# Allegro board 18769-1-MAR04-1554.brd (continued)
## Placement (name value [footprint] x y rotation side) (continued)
PU5301  RT5797ALGQW-GP  [DFN8-G125065H32]  25.77 47.3 270 bottom
PU8551  RT8816BGQW-GP  [QFN20-G1D75H32]  145.41 28.88 90 bottom
PU8552  FDMS3600-02-RJK0215-COLAY-GP  [PPAK-8P-G5324H44-COLAY]  150.71 35.74 270 bottom
PU8553  FDMS3600-02-RJK0215-COLAY-GP  [PPAK-8P-G5324H44-COLAY]  150.71 35.74 90 top
PU8554  FDMS3600-02-RJK0215-COLAY-GP  [PPAK-8P-G5324H44-COLAY]  138.9 35.74 90 bottom
PU8555  FDMS3600-02-RJK0215-COLAY-GP  [PPAK-8P-G5324H44-COLAY]  138.9 35.74 270 top
PU8601  RT5797ALGQW-GP  [DFN8-G125065H32]  134.13 79.38 270 bottom
PU8602  SY8288RAC-GP  [QFN20Z3-G1H36]  178.88 35.77 90 bottom
PU8603  RT5797ALGQW-GP  [DFN8-G125065H32]  139.04 85.8 90 bottom
Q401  2N7002KDW-1-GP  [SOT-363H44]  127.88 63.58 270 bottom
Q501  PJA138KA-GP  [SOT23DGS2D4H44]  52.31 38.52 180 bottom
Q502  2N7002K-2-GP  [SOT23DGS2D4H44]  50.88 41.17 0 bottom
Q1701  PJT138KA-GP  [SOT-363H44]  128.1 64.39 270 top
Q1702  2N7002KDW-1-GP  [SOT-363H44]  128.38 61.16 270 top
Q2408  2N7002K-2-GP  [SOT23DGS2D4H44]  23.74 15.33 0 top
Q2414  2N7002K-2-GP  [SOT23DGS2D4H44]  44.02 14.37 270 top
Q2416  2N7002KDW-1-GP  [SOT-363H44]  12.4 20.77 0 bottom
Q2505  2N7002K-2-GP  [SOT23DGS2D4H44]  13.08 8.63 180 bottom
Q2507  SM2421PSANC-TRG-GP  [SOT23DGS2D4H48]  20.21 4.65 90 bottom
Q2510  2N7002K-2-GP  [SOT23DGS2D4H44]  23.58 11.35 90 top
Q2601  2N7002KDW-1-GP  [SOT-363H44]  125.85 45.72 180 bottom
Q2602  2N7002K-2-GP  [SOT23DGS2D4H44]  126.68 44.24 0 top
Q2603  LMBT3904LT1G-GP  [SOT23CBE2D4H44]  94.81 78.35 0 bottom
Q4001  2N7002K-2-GP  [SOT23DGS2D4H44]  186.8 23.27 270 top
Q4002  PJA3415-GP  [SOT23DGS2D4H44]  195.19 15.44 180 bottom
Q4301  PJA138KA-GP  [SOT23DGS2D4H44]  28.1 51.53 180 bottom
Q4302  LMBT3904LT1G-GP  [SOT23CBE2D4H44]  31.54 52.42 0 bottom
Q4304  LMUN5212T1G-GP  [SOT323CBE2D2H40]  20.81 76.86 0 top
Q4305  LMUN5112T1G-GP-U  [SOT323CBE2D2H40]  29.67 81.64 90 top
Q5508  LMBT3904LT1G-GP  [SOT23CBE2D4H44]  41.16 75.42 180 top
Q5509  MMBT3906-3-GP  [SOT23CBE2D4H44]  37.04 69.25 270 top
Q5510  LMBT3904LT1G-GP  [SOT23CBE2D4H44]  43.75 76.15 180 bottom
Q5512  MMBT3906-3-GP  [SOT23CBE2D4H44]  47.18 72.65 180 bottom
Q5701  LMBT3904LT1G-GP  [SOT23CBE2D4H44]  16.44 59.05 270 bottom
Q5702  2N7002KDW-1-GP  [SOT-363H44]  15.46 55.81 180 bottom
Q5703  2N7002K-2-GP  [SOT23DGS2D4H44]  20.88 44.7 180 bottom
Q6401  LDTA144VLT1G-GP  [SOT23CBE2D4H44]  9.98 71.33 270 bottom
Q6402  LDTA144VLT1G-GP  [SOT23CBE2D4H44]  5.7 71.29 270 bottom
Q6403  PJA138KA-GP  [SOT23DGS2D4H44]  11.69 70.55 270 top
Q6404  PJT138KA-GP  [SOT-363H44]  13.86 71.16 270 bottom
Q6406  LMBT3904LT1G-GP  [SOT23CBE2D4H44]  17.29 65.75 180 bottom
Q6407  LMUN5112T1G-GP-U  [SOT323CBE2D2H40]  17.09 71.35 180 bottom
Q6501  PJA3402-R1-00001-GP  [SOT23DGS2D4H44]  36.49 10.29 270 bottom
Q6504  2N7002KDW-1-GP  [SOT-363H44]  124.55 12 180 bottom
Q6505  LDTA144VLT1G-GP  [SOT23CBE2D4H44]  50.35 11.14 90 bottom
Q6701  2N7002KDW-1-GP  [SOT-363H44]  15.39 52.23 180 bottom
Q7401  PJA3415-GP  [SOT23DGS2D4H44]  22.42 63.99 180 top
Q7404  2N7002KDW-1-GP  [SOT-363H44]  26.47 67.49 270 top
Q7405  2N7002KDW-1-GP  [SOT-363H44]  23.62 68.29 0 top
Q7406  PJT138KA-GP  [SOT-363H44]  20.77 69.75 180 top
Q7407  PJT138KA-GP  [SOT-363H44]  20.6 68.66 270 bottom
Q7601  PJA138KA-GP  [SOT23DGS2D4H44]  139.05 54.89 0 top
Q7901  PJT138KA-GP  [SOT-363H44]  137.73 51.49 90 top
Q7906  PJA138KA-GP  [SOT23DGS2D4H44]  139.05 57.39 0 top
Q7907  PJT138KA-GP  [SOT-363H44]  140.6 49.48 270 top
Q8101  PJA138KA-GP  [SOT23DGS2D4H44]  171.36 54.36 180 bottom
Q8504  2N7002K-2-GP  [SOT23DGS2D4H44]  144.52 77.85 180 bottom
Q8509  PJT138KA-GP  [SOT-363H44]  142.98 80.38 0 bottom
Q8601  PJA138KA-GP  [SOT23DGS2D4H44]  128.06 69.9 90 bottom
Q8602  2N7002K-2-GP  [SOT23DGS2D4H44]  132 64.57 180 bottom
Q8603  2N7002K-2-GP  [SOT23DGS2D4H44]  130.92 68.23 180 bottom
Q8605  2N7002K-2-GP  [SOT23DGS2D4H44]  150.46 79.08 270 bottom
Q8611  PJA3415-GP  [SOT23DGS2D4H44]  130.14 74.87 270 bottom
Q8612  PJT138KA-GP  [SOT-363H44]  131.43 71.31 180 bottom
Q8613  PJA138KA-GP  [SOT23DGS2D4H44]  126.66 66.44 180 bottom
Q8614  2N7002KDW-1-GP  [SOT-363H44]  153.4 81.43 225 bottom
Q8615  PJT138KA-GP  [SOT-363H44]  147.72 80.82 270 bottom
Q8616  PJT138KA-GP  [SOT-363H44]  188.02 41.05 90 bottom
Q9201  PJA3415-GP  [SOT23DGS2D4H44]  146.57 4.14 270 bottom
Q9202  2N7002K-2-GP  [SOT23DGS2D4H44]  146.57 7.63 90 bottom
R301  1KR2J-1-GP  [R402H16]  68.49 68.79 270 bottom
R302  499R2F-2-GP  [R402H16]  70.27 68.88 270 bottom
R303  100KR2J-1-GP  [R402H16]  110.29 36.43 90 top
R304  49D9R2F-GP  [R402H16]  100.18 50.1 0 top
R305  49D9R2F-GP  [R402H16]  103.54 49.76 270 top
R308  1KR2J-1-GP  [R402H16]  97.14 74.86 0 bottom
R310  51R2J-2-GP  [R402H16]  67.37 69.56 90 bottom
R317  51R2J-2-GP  [R402H16]  75.04 61.91 90 top
R401  24D9R2F-L-GP  [R402H16]  87.72 60.76 180 top
R402  10KR2J-L-GP  [R402H15]  124.03 64.62 90 bottom
R403  100KR2J-1-GP  [R402H16]  108.89 63.83 270 top
R501  200R2F-L-GP  [R402H16]  99.98 48.14 90 top
R502  80D6R2F-L-GP  [R402H16]  98.84 49.92 180 top
R503  162R2F-GP  [R402H16]  99.73 46.95 0 top
R506  10KR2J-L-GP  [R402H15]  52.08 43.21 90 bottom
R507  10KR2J-L-GP  [R402H15]  49.36 39.84 270 bottom
R601  49D9R2F-GP  [R402H16]  80.5 61.32 180 top
R709  -  [0R0402-PAD]  61.78 71.57 90 bottom
R719  100R2F-L1-GP-U  [R402H14]  87.21 63.63 0 top
R720  100R2F-L1-GP-U  [R402H14]  88 63.63 180 top
R723  54D9R2F-L1-GP  [R402H16]  68.2 70.73 0 bottom
R726  100R2F-L1-GP-U  [R402H14]  63.12 71.26 0 bottom
R727  56R2J-4-GP  [R402H16]  66.12 70.58 90 bottom
R728  220R2J-L2-GP  [R402H16]  63.97 71.12 180 bottom
R732  -  [0R0402-PAD]  69.98 70.15 90 bottom
R807  100R2F-L1-GP-U  [R402H14]  69.83 63.75 180 top
R808  100R2F-L1-GP-U  [R402H14]  68.04 63.74 0 top
R809  100R2F-L1-GP-U  [R402H14]  94.2 61.82 270 top
R810  100R2F-L1-GP-U  [R402H14]  95.7 60.5 270 top
R1103  -  [0R0603-PAD]  115.9 56.21 0 top
R1104  -  [0R0603-PAD]  126.16 55.88 90 top
R1201  240R2F-1-GP  [R402H16]  43.9 20.38 0 top
R1202  240R2F-1-GP  [R402H16]  44.67 20.38 0 top
R1203  240R2F-1-GP  [R402H16]  62.95 17.07 270 top
R1204  240R2F-1-GP  [R402H16]  62.95 17.84 270 top
R1205  68R2-GP  [R402H16]  48.54 20.43 180 top
R1206  68R2-GP  [R402H16]  53.1 20.38 180 top
R1207  68R2-GP  [R402H16]  67.74 16.57 180 top
R1208  68R2-GP  [R402H16]  72.08 16.49 180 top
R1214  38D3R2F-GP  [R402H16]  49.67 20.38 180 top
R1215  38D3R2F-GP  [R402H16]  69.3 16.57 180 top
R1216  38D3R2F-GP  [R402H16]  70.07 16.57 180 top
R1217  80D6R2F-L-GP  [R402H16]  61.56 23.8 180 top
R1218  80D6R2F-L-GP  [R402H16]  62.32 23.8 180 top
R1219  80D6R2F-L-GP  [R402H16]  60.79 23.8 180 top
R1220  80D6R2F-L-GP  [R402H16]  52.29 20.38 180 top
R1221  80D6R2F-L-GP  [R402H16]  51.44 20.39 180 top
R1222  8K2R2F-1-GP  [R402H16]  64.89 34.92 180 top
R1223  8K2R2F-1-GP  [R402H16]  64.07 34.92 0 top
R1224  10R2F-L1-GP  [R402H16]  64.45 36.11 270 top
R1225  24D9R2F-L-GP  [R402H16]  63.26 34.22 0 top
R1226  8K2R2F-1-GP  [R402H16]  79.59 21.14 180 top
R1227  8K2R2F-1-GP  [R402H16]  59.52 26.47 0 top
R1228  5D1R2F-GP  [R402H16]  61.28 35.35 90 top
R1229  24D9R2F-L-GP  [R402H16]  62.47 35.76 180 top
R1246  38D3R2F-GP  [R402H16]  50.49 20.38 180 top
R1249  80D6R2F-L-GP  [R402H16]  70.83 16.57 180 top
R1252  80D6R2F-L-GP  [R402H16]  68.54 16.57 180 top
R1301  240R2F-1-GP  [R402H16]  82.26 17.71 270 top
R1302  240R2F-1-GP  [R402H16]  82.26 16.95 270 top
R1303  240R2F-1-GP  [R402H16]  100.51 17.81 270 top
R1304  240R2F-1-GP  [R402H16]  100.51 17.05 270 top
R1305  68R2-GP  [R402H16]  87.38 16.45 180 top
R1306  68R2-GP  [R402H16]  91.67 16.45 180 top
R1307  68R2-GP  [R402H16]  106 16.57 180 top
R1308  68R2-GP  [R402H16]  111.59 16.56 180 top
R1310  38D3R2F-GP  [R402H16]  88.34 16.5 180 top
R1311  38D3R2F-GP  [R402H16]  106.77 16.57 180 top
R1312  38D3R2F-GP  [R402H16]  107.53 16.57 180 top
R1313  80D6R2F-L-GP  [R402H16]  100.16 21.9 180 top
R1314  80D6R2F-L-GP  [R402H16]  99.4 21.9 180 top
R1315  80D6R2F-L-GP  [R402H16]  98.64 21.9 180 top
R1316  80D6R2F-L-GP  [R402H16]  90.13 16.44 180 top
R1317  80D6R2F-L-GP  [R402H16]  90.89 16.44 180 top
R1318  80D6R2F-L-GP  [R402H16]  108.42 16.57 180 top
R1319  80D6R2F-L-GP  [R402H16]  109.18 16.57 180 top
R1320  8K2R2F-1-GP  [R402H16]  68.34 34.39 270 top
R1321  8K2R2F-1-GP  [R402H16]  68.34 35.15 90 top
R1322  24D9R2F-L-GP  [R402H16]  68.34 35.91 90 top
R1323  10R2F-L1-GP  [R402H16]  66.33 34.72 180 top
R1341  38D3R2F-GP  [R402H16]  89.11 16.5 180 top
R1501  20KR2J-L2-GP  [R402H16]  125.06 37.11 0 top
R1502  1KR2J-1-GP  [R402H16]  116.42 51.18 270 bottom
R1503  1KR2J-1-GP  [R402H16]  118.12 51.94 270 bottom
R1504  4K7R2J-L-GP  [R402H15]  121.24 56.92 180 bottom
R1505  20KR2J-L2-GP  [R402H16]  122.43 57.16 270 bottom
R1506  100KR2F-L3-GP  [R402H16]  106.74 38.3 0 bottom
R1507  1KR2J-1-GP  [R402H16]  106.74 39.87 180 bottom
R1508  100KR2F-L3-GP  [R402H16]  107.96 38.3 0 bottom
R1509  4K7R2J-L-GP  [R402H15]  107.96 39.9 180 bottom
R1510  100KR2F-L3-GP  [R402H16]  108.78 38.3 0 bottom
R1511  4K7R2J-L-GP  [R402H15]  108.8 39.9 0 bottom
R1512  4K7R2J-L-GP  [R402H15]  125.53 32.34 0 top
R1513  4K7R2J-L-GP  [R402H15]  122.64 46.97 90 bottom
R1514  4K7R2J-L-GP  [R402H15]  118.72 48.21 270 bottom
R1515  20KR2J-L2-GP  [R402H16]  166.8 25.25 90 top
R1517  1KR2J-1-GP  [R402H16]  64.29 69.51 90 bottom
R1518  1KR2J-1-GP  [R402H16]  62.64 70.02 270 bottom
R1519  10KR2J-L-GP  [R402H15]  119.77 54.38 90 bottom
R1520  4K7R2J-L-GP  [R402H15]  125.99 50.22 90 bottom
R1521  4K7R2J-L-GP  [R402H15]  125.47 49.44 90 bottom
R1522  4K7R2J-L-GP  [R402H15]  124.14 53.8 0 bottom
R1523  20KR2J-L2-GP  [R402H16]  125.82 54.12 180 bottom
R1524  100KR2F-L3-GP  [R402H16]  101.95 34.62 180 top
R1525  20KR2J-L2-GP  [R402H16]  101.1 34.98 0 top
R1527  1KR2J-1-GP  [R402H16]  126.13 49.54 90 top
R1551  4K7R2J-L-GP  [R402H15]  117.94 56.56 180 bottom
R1552  20KR2J-L2-GP  [R402H16]  119.39 56.05 270 bottom
R1553  20KR2J-L2-GP  [R402H16]  104.86 50.09 180 top
R1554  20KR2J-L2-GP  [R402H16]  121.63 53.61 90 bottom
R1555  20KR2J-L2-GP  [R402H16]  110.03 39.73 90 bottom
R1601  0R2J-L-GP  [R402H15]  107.87 60.76 0 top
R1602  0R2J-L-GP  [R402H15]  104.53 63.77 90 top
R1603  113R2F-GP  [R402H16]  106.09 63.73 0 top
R1604  100R2F-L1-GP-U  [R402H14]  107.29 64.29 270 top
R1605  -  [0R0402-PAD]  34.04 23.85 90 bottom
R1606  10KR2J-L-GP  [R402H15]  124.04 65.48 90 bottom
R1608  10KR2J-L-GP  [R402H15]  123.98 63.53 90 bottom
R1701  10KR2J-L-GP  [R402H15]  121.09 60.93 90 bottom
R1702  1KR2J-1-GP  [R402H16]  131.67 53.79 270 bottom
R1704  -  [0R0402-PAD]  130.01 54.12 90 bottom
R1706  -  [0R0402-PAD]  128.3 53.13 270 bottom
R1707  10KR2J-L-GP  [R402H15]  101.79 48.52 0 top
R1708  0R2J-2-GP  [R402H16]  114.91 35.49 0 top
R1713  -  [0R0402-PAD]  133.07 49.14 270 bottom
R1715  100KR2J-1-GP  [R402H16]  131.26 49.87 90 bottom
R1716  100KR2F-L3-GP  [R402H16]  90.34 72.65 0 bottom
R1717  10KR2J-L-GP  [R402H15]  127.3 56.92 180 bottom
R1718  100KR2F-L3-GP  [R402H16]  93.14 72.22 90 bottom
R1719  47KR2F-GP  [R402H16]  91.53 71.96 90 bottom
R1721  10KR2J-L-GP  [R402H15]  124.28 34.45 270 top
R1722  10KR2J-L-GP  [R402H15]  110.41 35.11 180 top
R1723  10KR2J-L-GP  [R402H15]  109.62 35.11 0 top
R1726  10KR2J-L-GP  [R402H15]  126.17 64.93 0 top
R1727  100KR2J-1-GP  [R402H16]  128.31 66.07 90 top
R1730  330KR2J-L1-GP  [R402H16]  116.85 37.88 90 bottom
R1731  100KR2F-L3-GP  [R402H16]  110.88 37.88 90 bottom
R1737  100KR2J-1-GP  [R402H16]  125.54 62.11 0 top
R1738  10KR2J-L-GP  [R402H15]  113.86 35.51 180 top
R1803  60D4R2F-GP  [R402H16]  112.66 70.41 0 bottom
R1805  33R2F-3-GP  [R402H16]  114.5 33.83 0 top
R1806  -  [0R0402-PAD]  122.52 57.97 270 bottom
R1815  10MR2J-L-GP  [R402H16]  105.62 36.6 90 top
R1819  10KR2J-L-GP  [R402H15]  124.18 58.36 90 bottom
R1820  10KR2J-L-GP  [R402H15]  116.15 36.42 270 top
R1821  10KR2J-L-GP  [R402H15]  113.07 35.51 180 top
R1837  150KR2J-GP  [R402H16]  111.21 39.34 0 bottom
R1839  33R2F-3-GP  [R402H16]  114.8 70.85 270 bottom
R1840  33R2F-3-GP  [R402H16]  114.8 71.64 270 bottom
R1841  1MR2J-1-GP  [R402H16]  115.38 72.45 270 bottom
R1901  200R2F-L-GP  [R402H16]  110.63 46.52 180 top
R1908  0R2J-L-GP  [R402H15]  174.25 14.16 270 top
R1909  1KR2J-1-GP  [R402H16]  174.76 19.67 270 top
R1910  10KR2J-L-GP  [R402H15]  118.09 49.6 90 bottom
R1911  10KR2J-L-GP  [R402H15]  118.09 50.36 270 bottom
R1912  33R2F-3-GP  [R402H16]  169.93 28.18 90 top
R1913  33R2F-3-GP  [R402H16]  167.07 29.03 270 top
R1920  0R2J-L-GP  [R402H15]  100.36 37.97 0 bottom
R1921  33R2F-3-GP  [R402H16]  173.04 19.04 180 top
R2002  10KR2J-L-GP  [R402H15]  35.05 28.43 180 bottom
R2003  -  [0R0402-PAD]  125.11 48.25 0 bottom
R2004  -  [0R0402-PAD]  136.74 48.85 90 bottom
R2008  10KR2J-L-GP  [R402H15]  119.87 58.87 0 bottom
R2009  10KR2J-L-GP  [R402H15]  130.34 59.93 270 bottom
R2010  10KR2J-L-GP  [R402H15]  128.13 59.61 270 bottom
R2011  10KR2J-L-GP  [R402H15]  122.61 49.58 90 bottom
R2012  10KR2J-L-GP  [R402H15]  119.82 49.66 90 bottom
R2013  10KR2J-L-GP  [R402H15]  122.84 47.95 90 bottom
R2014  10KR2J-L-GP  [R402H15]  121.17 48.12 90 bottom
R2015  10KR2J-L-GP  [R402H15]  119.82 52.75 90 bottom
R2016  10KR2J-L-GP  [R402H15]  122.61 52.73 90 bottom
R2017  10KR2J-L-GP  [R402H15]  119.82 51.98 90 bottom
R2018  10KR2J-L-GP  [R402H15]  122.61 51.94 90 bottom
R2022  10KR2J-L-GP  [R402H15]  119.82 51.2 90 bottom
R2025  -  [0R0402-PAD]  113.29 38.24 270 bottom
R2026  -  [0R0402-PAD]  113.47 37.05 270 bottom
R2027  -  [0R0402-PAD]  112.35 32.71 90 top
R2029  10KR2J-L-GP  [R402H15]  122.61 51.15 90 bottom
R2030  10KR2J-L-GP  [R402H15]  120.31 48.89 90 bottom
R2031  10KR2J-L-GP  [R402H15]  122.77 48.79 90 bottom
R2032  10KR2J-L-GP  [R402H15]  119.83 50.43 90 bottom
R2033  10KR2J-L-GP  [R402H15]  122.61 50.36 90 bottom
R2034  10KR2J-L-GP  [R402H15]  118.91 53.51 270 bottom
R2035  10KR2J-L-GP  [R402H15]  118.09 54.38 270 bottom
R2037  10KR2J-L-GP  [R402H15]  118.12 52.7 270 bottom
R2038  10KR2J-L-GP  [R402H15]  116.42 53.03 270 bottom
R2041  10KR2J-L-GP  [R402H15]  115.53 58.4 0 top
R2042  10KR2J-L-GP  [R402H15]  118.51 38.03 90 bottom
R2043  10KR2J-L-GP  [R402H15]  120.93 21.21 270 top
R2044  10KR2J-L-GP  [R402H15]  128.13 60.39 270 bottom
R2045  10KR2J-L-GP  [R402H15]  118.65 60.83 90 bottom
R2046  10KR2J-L-GP  [R402H15]  116.39 54.38 90 bottom
R2048  51KR2J-1-GP  [R402H16]  117.79 60.04 90 bottom
R2049  51KR2J-1-GP  [R402H16]  117.79 59.25 90 bottom
R2053  10KR2J-L-GP  [R402H15]  125.34 40.2 270 top
R2101  150R2F-1-GP  [R402H16]  125.74 47.87 270 top
R2102  -  [0R0402-PAD]  125.56 59.62 90 bottom
R2108  200R2F-L-GP  [R402H16]  109.96 56.09 90 top
R2110  10KR2J-L-GP  [R402H15]  125.56 60.38 90 bottom
R2111  10KR2J-L-GP  [R402H15]  126.02 58.62 90 bottom
R2112  10KR2J-L-GP  [R402H15]  123.28 56.32 270 bottom
R2113  10KR2J-L-GP  [R402H15]  113.79 52.28 180 top
R2114  10KR2J-L-GP  [R402H15]  115.05 52.66 90 top
R2115  10KR2J-L-GP  [R402H15]  107.25 54.89 180 top
R2116  10KR2J-L-GP  [R402H15]  107.56 57 180 top
R2117  10KR2J-L-GP  [R402H15]  125.86 56.39 90 bottom
R2118  10KR2J-L-GP  [R402H15]  123.28 55.55 270 bottom
R2119  -  [0R0402-PAD]  116.57 48.61 270 bottom
R2120  75KR2J-GP  [R402H16]  136.69 52.06 90 bottom
R2202  -  [0R0603-PAD]  111.16 63.33 180 top
R2203  -  [0R0603-PAD]  102.54 58.96 90 top
R2204  -  [0R0603-PAD]  112.3 55.98 270 top
R2205  -  [0R0603-PAD]  106.03 77.06 0 top
R2401  -  [0R0402-PAD]  35.05 17.85 90 bottom
R2402  -  [0R0402-PAD]  14.79 11.37 270 bottom
R2403  100KR2J-1-GP  [R402H16]  17.52 15.41 90 top
R2404  100KR2J-1-GP  [R402H16]  17.52 16.18 90 top
R2405  -  [0R0402-PAD]  21.28 31.8 0 bottom
R2406  -  [0R0402-PAD]  22.05 31.79 0 bottom
R2407  0R2J-L-GP  [R402H15]  27.95 9.58 180 top
R2408  10KR2J-L-GP  [R402H15]  27.09 9.58 0 top
R2410  0R2J-L-GP  [R402H15]  35.12 16.14 270 bottom
R2414  10KR2J-L-GP  [R402H15]  29.77 10.65 0 top
R2415  100KR2J-1-GP  [R402H16]  29.52 27.77 0 top
R2421  330R2J-3-GP  [R402H16]  20.15 19.97 90 top
R2423  330R2J-3-GP  [R402H16]  20.01 20.77 270 top
R2426  10KR2J-L-GP  [R402H15]  26.65 30.11 0 bottom
R2427  0R2J-L-GP  [R402H15]  25.22 20.11 180 top
R2430  10KR2J-L-GP  [R402H15]  25.21 22.63 180 top
R2432  1KR2J-1-GP  [R402H16]  13.98 27.81 270 bottom
R2434  100KR2J-1-GP  [R402H16]  24.25 30.45 0 top
R2435  100KR2J-1-GP  [R402H16]  15.52 22.41 270 bottom
R2437  43R2J-GP  [R402H16]  19.74 12.32 0 top
R2440  -  [0R0402-PAD]  34.15 12.42 270 bottom
R2441  100KR2F-L3-GP  [R402H16]  17.16 18.44 270 top
R2442  27KR2F-L-GP  [R402H16]  19.72 18.27 270 top
R2443  37K4R2F-1-GP  [R402H16]  14.75 21.47 90 bottom
R2444  100KR2F-L3-GP  [R402H16]  14.54 20.29 0 bottom
R2445  -  [0R0402-PAD]  17.1 21.68 270 top
R2446  -  [0R0603-PAD]  27.13 30.33 0 top
R2447  -  [0R0402-PAD]  25.11 30.1 0 bottom
R2449  10KR2F-2-GP  [R402H16]  24.44 22.63 180 top
R2451  100KR2J-1-GP  [R402H16]  18.66 26.67 180 top
R2452  100KR2J-1-GP  [R402H16]  60.12 2.5 180 top
R2453  100KR2J-1-GP  [R402H16]  61.01 2.5 0 top
R2454  100KR2J-1-GP  [R402H16]  19.79 22.1 90 top
R2455  100KR2J-1-GP  [R402H16]  35.81 12.4 270 bottom
R2456  100KR2J-1-GP  [R402H16]  37.27 17.42 180 bottom
R2457  115KR2F-GP  [R402H16]  36.99 15.22 270 bottom
R2460  10KR2J-L-GP  [R402H15]  22.42 27.8 0 top
R2461  0R2J-L-GP  [R402H15]  15.23 25.61 0 bottom
R2463  1KR2J-1-GP  [R402H16]  19.84 22.92 270 top
R2471  0R2J-L-GP  [R402H15]  25.89 30.11 180 bottom
R2473  -  [0R0402-PAD]  16.93 23.8 180 top
R2477  -  [0R0402-PAD]  23.2 27.64 0 top
R2480  100KR2J-1-GP  [R402H16]  32.08 13.24 90 top
R2482  -  [0R0402-PAD]  34.71 20.14 90 bottom
R2489  100KR2J-1-GP  [R402H16]  15.88 11.66 90 top
R2495  -  [0R0402-PAD]  20.14 23.8 270 top
R2497  100KR2J-1-GP  [R402H16]  19.73 25.01 0 top
R2503  15R2F-2-GP  [R402H16]  127.89 29.16 90 bottom
R2504  10MR2J-L-GP  [R402H16]  17.44 10.43 90 top
R2505  -  [0R0402-PAD]  17.37 6.89 90 bottom
R2506  33R2F-3-GP  [R402H16]  139.64 28.53 0 bottom
R2507  33R2F-3-GP  [R402H16]  139.03 24.9 180 bottom
R2508  33R2F-3-GP  [R402H16]  128.63 26.32 90 bottom
R2509  33R2F-3-GP  [R402H16]  128.63 25.56 90 bottom
R2510  1KR2J-1-GP  [R402H16]  15.77 10.27 270 top
R2511  4K7R2J-L-GP  [R402H15]  21.81 8.34 90 top
R2514  10KR2J-L-GP  [R402H15]  167.88 33.6 180 top
R2516  -  [0R0603-PAD]  171.59 35.79 180 bottom
R2518  100KR2J-1-GP  [R402H16]  19.63 3.87 270 top
R2519  4K7R2J-L-GP  [R402H15]  138.02 31.44 90 bottom
R2520  100KR2J-1-GP  [R402H16]  168.7 33.61 180 top
R2567  1MR2J-1-GP  [R402H16]  24.54 4.62 270 top
R2601  -  [0R0402-PAD]  126.65 41.98 180 top
R2603  7K5R2F-1-GP  [R402H16]  127.72 33.89 0 bottom
R2604  7K5R2F-1-GP  [R402H16]  129.51 36.93 0 bottom
R2612  -  [0R0603-PAD]  193.03 37.2 270 top
R2701  -  [0R0805-PAD]  181.01 23.05 0 top
R2702  100KR2J-1-GP  [R402H16]  188.25 10.47 90 top
R2703  -  [0R0603-PAD]  187.4 8.27 90 top
R2704  -  [0R0603-PAD]  192.35 9.84 90 top
R2705  -  [0R0603-PAD]  192.35 11.12 90 top
R2706  -  [0R0603-PAD]  192.35 12.4 90 top
R2707  -  [0R0805-PAD]  182.83 23.06 0 top
R2708  -  [0R0402-PAD]  183.29 9.53 180 top
R2709  -  [0R0402-PAD]  186.55 17.57 0 top
R2710  100KR2J-1-GP  [R402H16]  178.84 11.47 0 top
R2711  200KR2F-L-GP  [R402H16]  179.72 10.44 180 top
R2712  -  [0R0402-PAD]  178.71 20.13 0 top
R2715  -  [0R0603-PAD]  174.58 11.92 0 top
R2716  100KR2J-1-GP  [R402H16]  176.53 12.63 90 top
R2717  100KR2J-1-GP  [R402H16]  177.54 20.57 90 top
R2719  -  [0R0402-PAD]  185.73 20.24 0 top
R2723  22R2J-L1-GP  [R402H16]  176.94 15.77 90 top
R2724  22R2J-L1-GP  [R402H16]  176.94 13.69 90 top
R2734  -  [0R0402-PAD]  175.71 4.79 0 top
R2735  1KR2J-1-GP  [R402H16]  178.61 9.2 180 top
R2741  -  [0R0402-PAD]  168.17 4.47 90 top
R3301  -  [0R0603-PAD]  4.01 12.5 270 bottom
R3306  0R2J-L-GP  [R402H15]  10.39 18.34 0 bottom
R3307  0R2J-L-GP  [R402H15]  9.61 18.17 0 bottom
R3308  0R2J-L-GP  [R402H15]  8.77 17.92 0 bottom
R3309  0R2J-L-GP  [R402H15]  6.75 17.29 90 bottom
R3310  0R2J-L-GP  [R402H15]  5.25 17.8 0 bottom
R3311  0R2J-L-GP  [R402H15]  4.47 17.82 0 bottom
R3314  0R2J-L-GP  [R402H15]  13.69 12.99 270 bottom
R3315  0R2J-L-GP  [R402H15]  8.15 9.37 0 bottom
R3316  0R2J-L-GP  [R402H15]  4.81 7.6 0 bottom
R3317  0R2J-L-GP  [R402H15]  3.5 7.33 0 bottom
R3318  0R2J-L-GP  [R402H15]  2.71 7.33 0 bottom
R3319  0R2J-L-GP  [R402H15]  9.88 9.68 0 bottom
R3320  0R2J-L-GP  [R402H15]  8.92 9.58 0 bottom
R3321  -  [0R0402-PAD]  5.09 15.48 180 bottom
R3322  0R2J-L-GP  [R402H15]  12.08 13.96 270 bottom
R3323  0R2J-L-GP  [R402H15]  12.07 14.73 270 bottom
R3324  0R2J-L-GP  [R402H15]  1.83 16.09 0 bottom
R3325  10KR2J-L-GP  [R402H15]  12.11 10.95 270 bottom
R3326  0R2J-L-GP  [R402H15]  10.71 9.67 180 bottom
R3329  -  [0R0402-PAD]  12.1 11.75 90 bottom
R3331  1KR2F-3-GP  [R402H16]  3.09 19.05 270 bottom
R3332  1KR2F-3-GP  [R402H16]  3.03 18.26 90 bottom
R3333  1KR2F-3-GP  [R402H16]  11.06 16.65 0 bottom
R4005  1KR2J-1-GP  [R402H16]  37.45 61.6 0 bottom
R4006  20KR2F-L-GP  [R402H16]  16.42 27.27 180 top
R4009  10KR2J-L-GP  [R402H15]  17.35 25.91 90 top
R4010  0R2J-L-GP  [R402H15]  68.38 11.56 90 bottom
R4011  -  [0R0402-PAD]  36.66 61.57 0 bottom
R4024  0R2J-L-GP  [R402H15]  133.31 82.87 180 top
R4034  10KR2J-L-GP  [R402H15]  188.1 24.54 0 top
R4035  20KR2J-L2-GP  [R402H16]  188.77 22.76 0 top
R4036  -  [0R0603-PAD]  139.95 86.51 180 top
R4039  -  [0R0402-PAD]  134.79 31.73 180 bottom
R4040  0R2J-L-GP  [R402H15]  131 32.99 0 bottom
R4041  20KR2J-L2-GP  [R402H16]  130.16 33.01 0 bottom
R4043  -  [0R0603-PAD]  107.69 80.2 270 top
R4045  -  [0R1206-PAD]  109.96 79.73 0 top
R4302  15KR2F-GP  [R402H16]  29.27 53.23 180 bottom
R4303  10KR2J-L-GP  [R402H15]  30.44 50.91 0 bottom
R4304  2K2R2J-2-GP  [R402H16]  16.22 48.95 0 bottom
R4305  33R2J-2-GP  [R402H16]  16.98 48.95 0 bottom
R4306  33R2J-2-GP  [R402H16]  27.24 50.76 0 top
R4307  240KR3-GP  [R603H22]  30.72 78.62 270 top
R4308  47KR2F-GP  [R402H16]  27.99 80.76 270 top
R4309  100KR2J-1-GP  [R402H16]  27.92 51.94 270 top
R4310  100KR2J-1-GP  [R402H16]  23.61 68.66 90 bottom
R4316  20KR2J-L2-GP  [R402H16]  26.53 79.06 180 top
R4317  -  [0R0603-PAD]  24.65 50.92 270 bottom
R4327  100R2J-2-GP  [R402H14]  86.58 13.5 90 top
R4376  470KR2F-GP  [R402H16]  30.18 57.16 180 top
R4377  84K5R2F-GP  [R402H16]  32.11 57.96 270 top
R4378  100KR2J-1-GP  [R402H16]  32.41 59.54 90 top
R4502  -  [0R0402-PAD]  85.86 10.3 0 bottom
R4503  -  [0R0402-PAD]  81.04 6.13 90 top
R5001  0R6J-L-GP  [R1206H26]  97.63 84.94 180 bottom
R5101  0R6J-L-GP  [R1206H26]  40.59 37.19 90 bottom
R5501  -  [0R0603-PAD]  59.65 80.92 270 top
R5502  0R2J-L-GP  [R402H15]  63.61 84.87 90 top
R5504  100KR2J-1-GP  [R402H16]  47.33 78.57 0 top
R5508  -  [0R0805-PAD]  61.96 80.81 180 top
R5510  -  [0R0402-PAD]  55.61 76.44 270 bottom
R5511  -  [0R0603-PAD]  58.51 78.45 0 top
R5512  -  [0R0402-PAD]  52.86 78.94 90 top
R5517  4K7R2J-L-GP  [R402H15]  50.49 79.74 0 top
R5518  4K7R2J-L-GP  [R402H15]  48.81 78.54 90 top
R5521  0R2J-L-GP  [R402H15]  49.72 79.77 0 top
R5522  0R2J-L-GP  [R402H15]  48.93 79.77 0 top
R5532  200KR2J-L1-GP  [R402H16]  49.95 72.22 270 bottom
R5533  10KR2J-L-GP  [R402H15]  49.03 73.82 90 bottom
R5534  4K7R2J-L-GP  [R402H15]  42.2 73.92 180 top
R5535  100KR2J-1-GP  [R402H16]  41.79 72.34 180 top
R5536  -  [0R0402-PAD]  40.12 72.88 0 top
R5537  200KR2J-L1-GP  [R402H16]  37.79 72.9 180 top
R5538  10KR2J-L-GP  [R402H15]  36.26 71.34 270 top
R5539  4K7R2J-L-GP  [R402H15]  46.27 76.03 90 bottom
R5540  -  [0R0402-PAD]  34.12 68.68 0 top
R5546  0R5J-5-GP  [R805H24]  42.1 81.49 270 top
R5558  1MR2J-1-GP  [R402H16]  40.91 72.75 0 top
R5701  0R2J-L-GP  [R402H15]  21.42 53.27 270 top
R5702  0R2J-L-GP  [R402H15]  21.42 52.51 270 top
R5703  0R2J-L-GP  [R402H15]  21.3 51.49 270 top
R5704  0R2J-L-GP  [R402H15]  21.3 50.73 270 top
R5705  0R2J-L-GP  [R402H15]  21.42 54.92 270 top
R5706  0R2J-L-GP  [R402H15]  21.42 54.16 270 top
R5707  0R2J-L-GP  [R402H15]  21.3 49.97 270 top
R5708  0R2J-L-GP  [R402H15]  21.3 49.2 270 top
R5710  200KR2F-L-GP  [R402H16]  18.81 61.39 90 top
R5711  150KR2F-L-GP  [R402H16]  18.82 60.56 90 top
R5712  10KR2J-L-GP  [R402H15]  20.58 59.61 90 top
R5718  0R2J-2-GP  [R402H16]  19.42 46.56 90 bottom
R6101  22R2J-L1-GP  [R402H16]  168.11 24.08 0 top
R6102  22R2J-L1-GP  [R402H16]  167.7 26.45 0 top
R6103  100KR2J-1-GP  [R402H16]  168.2 22.2 0 top
R6104  -  [0R0402-PAD]  163.56 17.95 270 top
R6105  -  [0R0402-PAD]  163.56 17.18 270 top
R6106  0R2J-L-GP  [R402H15]  167.97 16.5 270 top
R6107  0R2J-L-GP  [R402H15]  170.25 19.21 270 top
R6108  0R2J-L-GP  [R402H15]  170.26 19.99 270 top
R6109  0R2J-L-GP  [R402H15]  170.27 21.37 270 top
R6110  0R2J-L-GP  [R402H15]  167.01 18.83 0 top
R6111  33R2J-2-GP  [R402H16]  137.56 51.23 270 bottom
R6112  33R2J-2-GP  [R402H16]  137.54 50.46 270 bottom
R6113  10KR2J-L-GP  [R402H15]  166.7 16.17 180 top
R6114  -  [0R0805-PAD]  165.2 14.38 90 top
R6115  10KR2J-L-GP  [R402H15]  165.9 16.18 180 top
R6117  33R2J-2-GP  [R402H16]  165.05 27.33 0 top
R6118  10KR2J-L-GP  [R402H15]  166.85 26.43 0 top
R6119  71K5R2F-1-GP  [R402H16]  167.27 27.64 90 top
R6120  75KR2F-GP  [R402H16]  169.95 28.99 270 top
R6121  20KR2J-L2-GP  [R402H16]  127.15 55.33 0 bottom
R6122  20KR2J-L2-GP  [R402H16]  125.36 54.42 0 top
R6123  20KR2J-L2-GP  [R402H16]  166.91 23.64 90 top
R6124  0R1J-GP  [R0201H12]  117.78 72.13 270 bottom
R6301  -  [0R0402-PAD]  117.5 30.01 90 top
R6302  0R5J-5-GP  [R805H24]  117.95 18.57 270 top
R6303  10KR2J-L-GP  [R402H15]  117.46 30.84 90 top
R6304  10KR2J-L-GP  [R402H15]  115.86 30.02 270 top
R6305  100KR2F-L3-GP  [R402H16]  115.86 33.62 180 top
R6314  0R2J-L-GP  [R402H15]  117.2 17.08 270 top
R6401  499R2F-2-GP  [R402H16]  3.62 72.3 0 bottom
R6402  680R2F-GP  [R402H16]  3.62 70.69 0 bottom
R6404  2MR2F-GP  [R402H16]  17.51 65.71 270 top
R6405  10KR2J-L-GP  [R402H15]  19.17 71.16 270 bottom
R6406  10KR2J-L-GP  [R402H15]  13.99 71.96 270 top
R6413  150R2F-1-GP  [R402H16]  17.64 72.65 90 top
R6419  0R2J-L-GP  [R402H15]  12.02 70.66 0 bottom
R6421  -  [0R0402-PAD]  15.38 72.95 180 bottom
R6422  -  [0R0402-PAD]  13.17 69.12 90 bottom
R6425  330KR2F-L-GP  [R402H16]  18.16 63.79 90 bottom
R6426  330R2J-3-GP  [R402H16]  16.49 70.65 270 top
R6502  -  [0R0603-PAD]  118.63 7.77 90 top
R6505  0R2J-L-GP  [R402H15]  126.27 12.62 0 bottom
R6506  0R2J-L-GP  [R402H15]  122.79 12.16 180 bottom
R6507  51KR2J-1-GP  [R402H16]  13.42 16.67 180 bottom
R6508  100KR2J-1-GP  [R402H16]  12.64 16.68 180 bottom
R6509  100KR2J-1-GP  [R402H16]  38.53 10.37 180 bottom
R6510  0R2J-L-GP  [R402H15]  124.59 15.63 180 bottom
R6511  10KR2J-L-GP  [R402H15]  120.04 5.93 270 top
R6513  1KR2J-1-GP  [R402H16]  61.89 2.41 180 top
R6601  0R2J-L-GP  [R402H15]  188.12 4.84 90 top
R6602  0R2J-L-GP  [R402H15]  188.12 5.63 90 top
R6603  -  [0R0402-PAD]  174.08 29.66 90 top
R6604  0R2J-L-GP  [R402H15]  174.48 30.87 0 top
R6605  -  [0R0402-PAD]  125.82 62.08 270 bottom
R6606  0R2J-L-GP  [R402H15]  189.98 3.83 90 top
R6607  -  [0R0402-PAD]  172.35 30.46 90 top
R6608  0R1J-GP  [R0201H12]  177.76 6.28 0 top
R6609  0R1J-GP  [R0201H12]  177.25 6.28 0 top
R6610  0R1J-GP  [R0201H12]  40.35 57.97 0 bottom
R6611  0R1J-GP  [R0201H12]  40.86 57.97 0 bottom
R6612  0R1J-GP  [R0201H12]  118.62 19.73 90 top
R6613  0R1J-GP  [R0201H12]  118.62 20.24 90 top
R6614  0R1J-GP  [R0201H12]  36.08 39.66 90 top
R6615  0R1J-GP  [R0201H12]  37.35 39.63 270 top
R6616  0R1J-GP  [R0201H12]  100.99 85.86 270 bottom
R6617  0R1J-GP  [R0201H12]  100.99 86.4 270 bottom
R6618  0R1J-GP  [R0201H12]  40.41 69.62 0 bottom
R6619  0R1J-GP  [R0201H12]  39.9 69.62 0 bottom
R6620  0R1J-GP  [R0201H12]  45.5 81.92 270 top
R6621  0R1J-GP  [R0201H12]  45.5 81.41 270 top
R6622  0R1J-GP  [R0201H12]  94.84 87.37 180 bottom
R6623  0R1J-GP  [R0201H12]  95.35 87.36 180 bottom
R6624  0R1J-GP  [R0201H12]  124.75 9.99 270 top
R6625  0R1J-GP  [R0201H12]  124.76 9.48 270 top
R6626  -  [0R0402-PAD]  194.07 18.7 90 top
R6701  1MR2J-1-GP  [R402H16]  14.92 45.65 180 bottom
R6702  680KR2F-GP  [R402H16]  14.49 47.35 0 bottom
R6742  100KR2J-1-GP  [R402H16]  15.7 47.2 0 top
R6743  100KR2J-1-GP  [R402H16]  14.73 45.91 0 top
R6744  -  [0R0402-PAD]  14.48 47.16 270 top
R6745  0R2J-L-GP  [R402H15]  12.43 47.55 0 top
R6801  0R2J-L-GP  [R402H15]  32.71 12.26 90 top
R6802  0R2J-L-GP  [R402H15]  30.44 23.92 180 top
R6803  0R2J-L-GP  [R402H15]  31.88 23.98 180 top
R7001  -  [0R0402-PAD]  194.84 32.7 180 top
R7002  -  [0R0402-PAD]  194.98 27.52 0 top
R7003  -  [0R0402-PAD]  192.13 29.95 270 top
R7004  -  [0R0402-PAD]  192.12 30.75 270 top
R7005  -  [0R0402-PAD]  141.97 84.83 90 bottom
R7006  -  [0R0402-PAD]  144.27 86.34 270 bottom
R7008  10KR2J-L-GP  [R402H15]  194.2 27.49 180 top
R7016  10KR2J-L-GP  [R402H15]  193.4 27.5 0 top
R7101  100KR2J-1-GP  [R402H16]  19.47 38.89 0 bottom
R7102  100KR2J-1-GP  [R402H16]  20.26 38.89 0 bottom
R7114  -  [0R0402-PAD]  21.67 42.61 180 top
R7116  -  [0R0402-PAD]  20.91 42.61 180 top
R7118  10KR2J-L-GP  [R402H15]  16.48 39.03 0 top
R7119  220KR2F-L-GP  [R402H16]  11.8 38.63 180 top
R7120  220KR2F-L-GP  [R402H16]  11.8 37.06 0 top
R7121  4K7R2J-L-GP  [R402H15]  16.1 36.44 270 bottom
R7122  220KR2F-L-GP  [R402H16]  11.77 31.25 180 top
R7123  220KR2F-L-GP  [R402H16]  11.77 29.65 0 top
R7124  -  [0R0402-PAD]  23.9 34.79 90 bottom
R7140  1KR2J-1-GP  [R402H16]  14.23 34.17 180 top
R7141  1KR2J-1-GP  [R402H16]  14.99 34.17 0 top
R7142  1KR2J-1-GP  [R402H16]  15 34.83 180 bottom
R7143  1KR2J-1-GP  [R402H16]  16.53 35.33 90 bottom
R7144  1KR2J-1-GP  [R402H16]  20.02 33.58 0 bottom
R7145  1KR2J-1-GP  [R402H16]  23.87 33.2 90 top
R7146  1KR2J-1-GP  [R402H16]  24.52 34.3 90 top
R7147  1KR2J-1-GP  [R402H16]  18.06 30.66 180 top
R7149  -  [0R0402-PAD]  20.15 42.61 180 top
R7151  -  [0R0402-PAD]  17.59 41.74 180 top
R7152  1KR2J-1-GP  [R402H16]  18.82 30.66 180 top
R7153  -  [0R0402-PAD]  16.8 41.74 180 top
R7170  1KR2J-1-GP  [R402H16]  19.26 33.55 0 bottom
R7171  1KR2J-1-GP  [R402H16]  21.86 36.31 90 bottom
R7172  1KR2J-1-GP  [R402H16]  21.72 35.44 90 bottom
R7173  1KR2J-1-GP  [R402H16]  21.9 37.57 90 bottom
R7174  1KR2J-1-GP  [R402H16]  22.34 39.13 90 bottom
R7201  -  [0R0402-PAD]  31.89 62.34 90 bottom
R7202  100KR2J-1-GP  [R402H16]  26.64 61.9 0 top
R7204  0R2J-2-GP  [R402H16]  25.01 59.26 180 top
R7206  15KR2F-GP  [R402H16]  32.52 61.55 270 bottom
R7208  1MR2J-1-GP  [R402H16]  20.93 61.61 270 bottom
R7211  -  [0R0402-PAD]  22.95 56.43 90 bottom
R7212  -  [0R0402-PAD]  22.34 57.54 270 top
R7214  1MR2J-1-GP  [R402H16]  18.71 61.93 270 bottom
R7215  100KR2F-L3-GP  [R402H16]  27.11 68.25 270 bottom
R7216  -  [0R0402-PAD]  24.74 67.16 180 bottom
R7217  -  [0R0402-PAD]  23.87 67.32 180 bottom
R7218  0R2J-2-GP  [R402H16]  26.55 66.9 0 bottom
R7219  0R2J-2-GP  [R402H16]  25.53 67.61 0 bottom
R7220  -  [0R0402-PAD]  32.32 54.53 90 bottom
R7221  -  [0R0402-PAD]  32.35 55.3 90 bottom
R7222  10KR2J-L-GP  [R402H15]  29.65 61.07 0 top
R7223  43KR2F-GP  [R402H16]  32.42 60.51 90 top
R7224  10KR2J-L-GP  [R402H15]  28.94 63.78 0 top
R7225  3K3R2J-3-GP  [R402H16]  32.88 66.53 90 top
R7226  3K3R2J-3-GP  [R402H16]  34.08 66.86 0 top
R7227  -  [0R0402-PAD]  23.28 62.24 180 top
R7228  3K3R2J-3-GP  [R402H16]  33.16 65.08 270 bottom
R7229  -  [0R0402-PAD]  18.91 61.03 90 bottom
R7230  3K3R2J-3-GP  [R402H16]  32.88 65.74 90 top
R7231  1MR2J-1-GP  [R402H16]  18.1 62.79 90 bottom
R7235  -  [0R0402-PAD]  27.35 67.02 180 bottom
R7236  -  [0R0402-PAD]  25.87 61.75 0 top
R7237  1MR2J-1-GP  [R402H16]  29.28 54.94 0 bottom
R7241  1MR2J-1-GP  [R402H16]  30.89 54.92 0 bottom
R7242  1MR2J-1-GP  [R402H16]  30.08 54.94 0 bottom
R7243  10KR2J-L-GP  [R402H15]  19.6 63.94 90 top
R7245  1MR2J-1-GP  [R402H16]  28.84 62.25 90 top
R7247  10KR2J-L-GP  [R402H15]  17.74 63.81 90 top
R7250  1MR2J-1-GP  [R402H16]  20.18 62.46 180 top
R7330  2MR2F-GP  [R402H16]  11.13 33.51 90 top
R7331  2MR2F-GP  [R402H16]  19.33 42.74 270 bottom
R7402  200KR2F-L-GP  [R402H16]  17.8 69.32 180 top
R7403  -  [0R0402-PAD]  19.85 64.73 90 top
R7404  1MR2F-GP  [R402H16]  19.25 66.32 270 top
R7405  100KR2F-L3-GP  [R402H16]  21.53 67.75 270 top
R7406  100KR2F-L3-GP  [R402H16]  21.85 66.47 90 top
R7407  1MR2F-GP  [R402H16]  29.05 70.22 180 bottom
R7408  200KR2F-L-GP  [R402H16]  17.79 68.61 180 bottom
R7409  200KR2F-L-GP  [R402H16]  27.3 70.06 180 top
R7410  200KR2F-L-GP  [R402H16]  22.41 70.53 180 top
R7411  1MR2F-GP  [R402H16]  23.01 76.24 180 top
R7422  1MR2F-GP  [R402H16]  22.69 70 270 bottom
R7423  100KR2F-L3-GP  [R402H16]  26.54 70.06 0 top
R7424  100KR2F-L3-GP  [R402H16]  20.71 70.8 0 bottom
R7425  100KR2F-L3-GP  [R402H16]  25.75 70.05 0 top
R7426  100KR2F-L3-GP  [R402H16]  24.97 70.06 0 top
R7427  100KR2F-L3-GP  [R402H16]  21.48 70.8 0 bottom
R7428  100KR2F-L3-GP  [R402H16]  19.53 71.62 270 top
R7601  2K49R2F-2-L-GP  [R402H16]  152.47 79.42 135 bottom
R7602  10KR2F-2-GP  [R402H16]  143.73 75.37 45 bottom
R7603  10KR2J-L-GP  [R402H15]  138.04 57.66 0 bottom
R7604  0R2J-L-GP  [R402H15]  136.27 76.07 270 bottom
R7606  10KR2J-L-GP  [R402H15]  136.27 74.22 270 bottom
R7701  10KR2J-L-GP  [R402H15]  160.93 46.86 45 bottom
R7805  40D2R2F-GP  [R402H16]  174.38 67.18 0 top
R7806  60D4R2F-GP  [R402H16]  175.2 67.76 180 top
R7807  40D2R2F-GP  [R402H16]  176.02 67.78 180 top
R7808  60D4R2F-GP  [R402H16]  173.6 67.19 180 top
R7809  60D4R2F-GP  [R402H16]  162.57 62.03 90 top
R7816  10KR2F-2-GP  [R402H16]  182.27 61.96 0 top
R7820  10KR2F-2-GP  [R402H16]  180.61 61.96 180 top
R7821  10KR2F-2-GP  [R402H16]  178.45 70.06 0 top
R7824  10KR2F-2-GP  [R402H16]  180.07 70.01 180 top
R7901  10KR2J-L-GP  [R402H15]  161.41 44.97 45 bottom
R7902  10KR2J-L-GP  [R402H15]  144.08 53.1 270 bottom
R7903  1MR2J-1-GP  [R402H16]  174.72 41.86 90 bottom
R7904  1KR2J-1-GP  [R402H16]  172.94 41.86 90 bottom
R7905  100KR2J-1-GP  [R402H16]  160.39 46.31 45 bottom
R7907  40K2R2F-GP  [R402H16]  157.14 56.93 135 top
R7908  100KR2F-L3-GP  [R402H16]  144.31 50.94 90 bottom
R7909  100KR2F-L3-GP  [R402H16]  141.09 49.93 270 bottom
R7910  100KR2J-1-GP  [R402H16]  173.22 52.56 0 bottom
R7911  100KR2F-L3-GP  [R402H16]  141.33 50.7 90 bottom
R7912  10KR2J-L-GP  [R402H15]  136.44 61.07 45 bottom
R7914  100KR2F-L3-GP  [R402H16]  141.32 48.39 270 bottom
R7915  100KR2F-L3-GP  [R402H16]  143.63 48.53 90 bottom
R7917  10KR2J-L-GP  [R402H15]  144.07 53.95 90 bottom
R7918  100KR2F-L3-GP  [R402H16]  171.84 51.11 90 bottom
R7919  100KR2F-L3-GP  [R402H16]  144.31 51.72 270 bottom
R7920  100KR2F-L3-GP  [R402H16]  173.56 49.51 90 bottom
R7921  100KR2F-L3-GP  [R402H16]  173.56 48.72 270 bottom
R7924  100KR2F-L3-GP  [R402H16]  171.88 49.52 270 bottom
R7925  100KR2F-L3-GP  [R402H16]  141.1 53 270 bottom
R7926  100KR2F-L3-GP  [R402H16]  141.11 53.77 90 bottom
R7927  10KR2J-L-GP  [R402H15]  149.77 49.41 0 bottom
R7928  100KR2F-L3-GP  [R402H16]  141.11 52.24 270 bottom
R7929  100KR2F-L3-GP  [R402H16]  141.34 51.47 90 bottom
R7932  100KR2F-L3-GP  [R402H16]  171.84 51.87 270 bottom
R7933  10KR2J-L-GP  [R402H15]  141.73 56.49 0 bottom
R7935  100KR2F-L3-GP  [R402H16]  171.84 50.35 90 bottom
R7937  0R2J-L-GP  [R402H15]  148.58 48.94 90 bottom
R7938  100KR2F-L3-GP  [R402H16]  141.08 49.16 270 bottom
R7939  100KR2F-L3-GP  [R402H16]  143.22 49.48 90 bottom
R7948  10KR2J-L-GP  [R402H15]  126.92 48.64 90 bottom
R7949  10KR2J-L-GP  [R402H15]  139.23 56.32 270 bottom
R7952  10KR2J-L-GP  [R402H15]  144.93 49.33 0 bottom
R7953  10KR2J-L-GP  [R402H15]  186.35 42.4 90 bottom
R7957  -  [0R0402-PAD]  139.84 52.45 0 top
R8101  40D2R2F-GP  [R402H16]  182.24 44.29 0 top
R8102  40D2R2F-GP  [R402H16]  183 44.29 0 top
R8104  931R2F-1-GP  [R402H16]  173.52 54.36 0 bottom
R8106  549R2F-GP  [R402H16]  175.42 52.35 90 bottom
R8107  1K33R2F-GP  [R402H16]  174.31 53.54 180 bottom
R8108  121R2F-GP  [R402H16]  183.81 44.25 0 top
R8110  -  [0R0402-PAD]  184.6 44.21 0 top
R8111  1KR2J-1-GP  [R402H16]  181.43 61.95 180 top
R8206  40D2R2F-GP  [R402H16]  179.13 86.79 0 top
R8208  40D2R2F-GP  [R402H16]  178.37 86.79 0 top
R8209  -  [0R0402-PAD]  178.66 86.52 0 bottom
R8210  1KR2J-1-GP  [R402H16]  179.29 70.01 180 top
R8213  121R2F-GP  [R402H16]  179.44 86.49 0 bottom
R8521  0R2J-L-GP  [R402H15]  144.48 78.99 0 top
R8523  -  [0R0402-PAD]  142.27 83.68 270 bottom
R8524  0R2J-L-GP  [R402H15]  141.63 84.11 0 top
R8525  -  [0R0402-PAD]  142.58 79.57 90 top
R8529  10KR2J-L-GP  [R402H15]  145.42 79.09 0 top
R8530  -  [0R0402-PAD]  144.52 82.93 0 bottom
R8531  0R2J-L-GP  [R402H15]  145.34 83.46 0 top
R8532  0R2J-L-GP  [R402H15]  147.11 83.56 0 top
R8533  0R2J-L-GP  [R402H15]  146.17 83.43 180 top
R8534  100KR2F-L3-GP  [R402H16]  148.39 83.37 180 bottom
R8541  10KR2J-L-GP  [R402H15]  141.28 80.09 180 bottom
R8604  1MR2J-1-GP  [R402H16]  187.62 39.86 0 top
R8611  0R2J-L-GP  [R402H15]  141.92 75.62 90 bottom
R8612  100KR2J-1-GP  [R402H16]  146.74 81.25 90 top
R8613  100KR2J-1-GP  [R402H16]  149.54 79.88 90 top
R8614  0R2J-L-GP  [R402H15]  142.12 77.43 180 bottom
R8615  0R2J-L-GP  [R402H15]  149.64 82.44 90 bottom
R8616  100KR2J-1-GP  [R402H16]  188.94 39.94 90 top
R8617  -  [0R0402-PAD]  145.39 79.55 0 bottom
R8618  100R2J-2-GP  [R402H14]  150.73 81.26 90 bottom
R8620  2K2R2J-2-GP  [R402H16]  126.08 70.39 0 bottom
R8621  -  [0R0402-PAD]  133.22 62.43 270 bottom
R8622  100R2J-2-GP  [R402H14]  188.07 43.45 180 bottom
R8623  100R2J-2-GP  [R402H14]  129.26 72 270 bottom
R8624  10R2J-L-GP  [R402H16]  149.6 76.94 90 bottom
R8625  10R2J-L-GP  [R402H16]  154.64 82.64 45 bottom
R8626  -  [0R0402-PAD]  140.27 75.65 270 bottom
R8634  10KR2J-L-GP  [R402H15]  131 66.35 0 bottom
R8635  10KR2J-L-GP  [R402H15]  130.01 77.02 270 bottom
R8637  10KR2J-L-GP  [R402H15]  133.23 61.65 90 bottom
R9101  D01R2J-L-GP  [R402-TO0D2H20]  177.22 26.49 180 top
R9102  0R2J-L-GP  [R402H15]  189.03 31.7 0 top
R9118  2K2R2F-GP  [R402H16]  183.79 33.38 270 top
R9121  0R2J-2-GP  [R402H16]  184.33 24.81 0 top
R9123  0R2J-L-GP  [R402H15]  179.75 31.82 270 top
R9124  0R2J-2-GP  [R402H16]  179.76 32.6 270 top
R9130  0R2J-L-GP  [R402H15]  177.94 29.93 90 top
R9131  0R2J-2-GP  [R402H16]  189.22 27.74 90 top
R9132  33R2J-2-GP  [R402H16]  180.07 25.5 90 top
R9133  33R2J-2-GP  [R402H16]  179.74 28.82 90 top
R9138  33R2J-2-GP  [R402H16]  179.77 30.18 90 top
R9148  10KR2J-L-GP  [R402H15]  177.09 29.11 90 top
R9151  10KR2J-L-GP  [R402H15]  179.77 30.97 90 top
R9201  100KR2J-1-GP  [R402H16]  142.03 9.04 0 top
R9209  0R2J-L-GP  [R402H15]  135.8 5.73 0 bottom
R9210  0R2J-L-GP  [R402H15]  135.04 5.73 0 bottom
R9212  100KR2J-1-GP  [R402H16]  147.89 6.36 0 bottom
R9213  0R3J-0-U-GP  [R603H22]  143.73 9.28 270 top
R9804  4K7R2F-GP  [R402H16]  176.09 27.56 180 top
R9805  1KR2F-3-GP  [R402H16]  176.19 24.88 90 top
R9806  0R2J-L-GP  [R402H15]  176.09 23.37 180 top
RAM1  K4E6E304EE-EGCF-GP-COLAY-U1  [BGA178M110115H40-COLAY-U1]  51.13 28.61 90 top
RAM2  K4E6E304EE-EGCF-GP-COLAY-U1  [BGA178M110115H40-COLAY-U1]  70.26 24.87 90 top
RAM3  K4E6E304EE-EGCF-GP-COLAY-U1  [BGA178M110115H40-COLAY-U1]  89.18 24.87 90 top
RAM4  K4E6E304EE-EGCF-GP-COLAY-U1  [BGA178M110115H40-COLAY-U1]  108.36 24.87 90 top
RN401  SRN2K2J-1-GP  [ARES2H16]  16.35 55.91 270 top
RN403  SRN2K2J-1-GP  [ARES2H16]  110.81 69.37 270 bottom
RN405  SRN10KJ-5-GP  [ARES2H18]  129.16 65.77 0 bottom
RN1201  SRN68J-3-GP  [ARES8-CN24]  54.97 20.31 0 top
RN1202  SRN68J-5-GP  [SMD-ARES4H18]  47.35 20.37 0 top
RN1203  SRN68J-5-GP  [SMD-ARES4H18]  73.25 16.5 0 top
RN1205  SRN68J-3-GP  [ARES8-CN24]  65.92 16.56 0 top
RN1206  SRN68J-5-GP  [SMD-ARES4H18]  45.81 20.38 0 top
RN1207  SRN68J-5-GP  [SMD-ARES4H18]  74.8 16.48 0 top
RN1301  SRN68J-3-GP  [ARES8-CN24]  93.46 16.52 0 top
RN1302  SRN68J-5-GP  [SMD-ARES4H18]  86.2 16.46 0 top
RN1303  SRN68J-5-GP  [SMD-ARES4H18]  110.36 16.53 0 top
RN1304  SRN68J-5-GP  [SMD-ARES4H18]  103.28 16.55 0 top
RN1306  SRN68J-5-GP  [SMD-ARES4H18]  84.67 16.44 0 top
RN1307  SRN68J-5-GP  [SMD-ARES4H18]  113.12 16.57 0 top
RN1308  SRN68J-5-GP  [SMD-ARES4H18]  104.82 16.53 0 top
RN1601  SRN10KJ-6-GP  [ARES8-CN24-MUH20]  113.62 61.21 90 top
RN1703  SRN100KJ-6-GP  [SMD-ARES4]  130.08 52.82 180 bottom
RN1704  SRN10KJ-5-GP  [ARES2H18]  111.89 35.91 0 top
RN1801  SRN20KJ-1-GP  [SMD-ARES4H20]  116.83 26.72 0 top
RN1806  SRN15J-GP  [ARES8-CN24-MUH20]  119.39 32.21 270 top
RN1807  SRN2K2J-4-GP  [ARES8-CN24-UH20]  111.92 58.08 90 top
RN1811  SRN2K2J-1-GP  [ARES2H16]  116.16 56.54 270 bottom
RN1813  SRN10KJ-6-GP  [ARES8-CN24-MUH20]  122.15 36.48 90 top
RN2007  SRN1KJ-7-GP  [SMD-ARES4H18]  111.67 53.72 270 top
RN2009  SRN10KJ-5-GP  [ARES2H18]  125.72 51.18 0 top
RN2402  SRN4K7J-8-GP  [SMD-ARES4H18]  21.22 27.75 180 top
RN2403  SRN10KJ-6-GP  [ARES8-CN24-MUH20]  44.43 2.4 0 top
RN2404  SRN10KJ-6-GP  [ARES8-CN24-MUH20]  40.42 2.53 0 top
RN2405  SRN100KJ-5-GP  [ARES8-CN24H20]  20.38 16.6 180 top
RN2409  SRN100KJ-5-GP  [ARES8-CN24H20]  47.07 2.41 0 top
RN2410  SRN100KJ-5-GP  [ARES8-CN24H20]  56.93 2.45 0 top
RN2411  SRN100KJ-5-GP  [ARES8-CN24H20]  52.26 2.41 0 top
RN2412  SRN100KJ-5-GP  [ARES8-CN24H20]  49.61 2.41 0 top
RN2413  SRN2K2J-1-GP  [ARES2H16]  20.97 12.31 0 top
RN2602  SRN2K2J-1-GP  [ARES2H16]  121.91 38.19 90 bottom
RN2901  SRN2K2J-1-GP  [ARES2H16]  190.36 11.78 180 top
RN2902  SRN4K7J-8-GP  [SMD-ARES4H18]  188.4 14.4 90 top
RN4302  SRN100J-3-GP  [SMD-ARES4H18]  111.48 11.56 90 top
RN5501  SRN100J-3-GP  [SMD-ARES4H18]  59.25 85.72 180 top
RN5502  SRN100KJ-5-GP  [ARES8-CN24H20]  60.16 87.79 180 top
RN5503  SRN33J-5-GP-U  [SMD-ARES4H18]  55.98 78.45 180 top
RN5504  SRN33J-5-GP-U  [SMD-ARES4H18]  64.48 82.73 0 top
RN5505  SRN100J-3-GP  [SMD-ARES4H18]  61.35 85.17 180 top
RN5701  SRN2K2J-1-GP  [ARES2H16]  15.98 68.19 90 top
RN5702  SRN470J-3-GP  [ARES8-CN24H20]  21.3 50.47 270 bottom
RN5703  SRN470J-3-GP  [ARES8-CN24H20]  21.04 53.9 270 bottom
RN6501  SRN10KJ-5-GP  [ARES2H18]  126.56 4.6 270 top
RN6502  SRN0J-6-GP  [SMD-ARES4H20]  126.58 6.72 90 top
RN6503  SRN2K2J-1-GP  [ARES2H16]  122 5.8 0 top
RN7202  SRN10KJ-5-GP  [ARES2H18]  27.06 64.6 90 top
RN7203  SRN100KJ-5-GP  [ARES8-CN24H20]  32.06 59.63 270 bottom
RN7206  SRN2K2J-1-GP  [ARES2H16]  34.25 63.17 270 bottom
RN7901  SRN4K7J-8-GP  [SMD-ARES4H18]  138.74 53.54 0 bottom
RN7904  SRN2K2J-1-GP  [ARES2H16]  162.65 53.19 45 top
RN7905  SRN2K2J-1-GP  [ARES2H16]  161.39 54.37 315 top
RN7910  SRN10KJ-5-GP  [ARES2H18]  141.21 54.92 90 bottom
RTC1  ETY-CON2-22-GP-U  [3703K-Q02N-11L-U]  12.6 4.42 90 bottom
SPK1  ACES-CON4-29-GP  [50224-0040N-001]  162.6 4.96 180 bottom
SSD1  SKT-NGFF75P-146-GP  [NFSM0-S6701-TP20]  117.34 25.14 90 bottom
TC4702  SE33U25VM-11-GP  [CT7343H83]  80.87 83.98 270 bottom
TC4805  SE33U25VM-11-GP  [CT7343H83]  35.91 52 180 bottom
TP302  TPAD14-OP-GP  [TPAD14-OP]  73.31 69.57 180 bottom
TP303  TPAD14-OP-GP  [TPAD14-OP]  71.87 68.34 180 bottom
TP304  TPAD14-OP-GP  [TPAD14-OP]  106.65 59.11 0 top
TP305  TPAD14-OP-GP  [TPAD14-OP]  75.75 69.21 180 bottom
TP306  TPAD14-OP-GP  [TPAD14-OP]  74.86 68.37 180 bottom
TP307  TPAD14-OP-GP  [TPAD14-OP]  73.49 68.35 180 bottom
TP308  TPAD14-OP-GP  [TPAD14-OP]  72.04 69.57 180 bottom
TP309  TPAD14-OP-GP  [TPAD14-OP]  75.03 63.06 0 top
TP310  TPAD14-OP-GP  [TPAD14-OP]  65.53 68.71 180 bottom
TP313  TPAD14-OP-GP  [TPAD14-OP]  79.44 62.51 0 top
TP314  TPAD14-OP-GP  [TPAD14-OP]  78.37 63.33 0 top
TP316  TPAD14-OP-GP  [TPAD14-OP]  77.47 61.96 0 top
TP317  TPAD14-OP-GP  [TPAD14-OP]  76.25 62.88 0 top
TP618  TPAD14-OP-GP  [TPAD14-OP]  74.58 69.57 180 bottom
TP619  TPAD14-OP-GP  [TPAD14-OP]  64.35 62.06 180 bottom
TP620  TPAD14-OP-GP  [TPAD14-OP]  113.52 39.7 180 bottom
TP1706  TPAD14-OP-GP  [TPAD14-OP]  102.58 40.05 180 bottom
TP1708  TPAD14-OP-GP  [TPAD14-OP]  105.75 38.1 180 bottom
TP1710  TPAD14-OP-GP  [TPAD14-OP]  102.28 46.03 0 top
TP1714  TPAD14-OP-GP  [TPAD14-OP]  102.9 48.59 0 top
TP1715  TPAD14-OP-GP  [TPAD14-OP]  101.08 45.8 0 top
TP1807  TPAD14-OP-GP  [TPAD14-OP]  89.78 70 180 bottom
TP1808  TPAD14-OP-GP  [TPAD14-OP]  89.62 68.7 180 bottom
TP1903  TPAD14-OP-GP  [TPAD14-OP]  99.13 37.17 180 bottom
TP2201  TPAD14-OP-GP  [TPAD14-OP]  105.07 39.11 180 bottom
TP2202  TPAD14-OP-GP  [TPAD14-OP]  105.2 40.33 180 bottom
TP2402  TPAD14-OP-GP  [TPAD14-OP]  29.7 29.49 180 top
TP4401  TPAD14-OP-GP  [TPAD14-OP]  151.1 16.77 0 top
TP4402  TPAD14-OP-GP  [TPAD14-OP]  153.21 11.14 180 bottom
TP4601  TPAD14-OP-GP  [TPAD14-OP]  51.1 68.93 90 bottom
TP7202  TPAD14-OP-GP  [TPAD14-OP]  29.5 56.47 180 bottom
TP7203  TPAD14-OP-GP  [TPAD14-OP]  24.91 57.02 180 bottom
TP7204  TPAD14-OP-GP  [TPAD14-OP]  24.41 55.89 180 bottom
TP7205  TPAD14-OP-GP  [TPAD14-OP]  17.18 61.42 270 bottom
TP7614  TPAD14-OP-GP  [TPAD14-OP]  138.52 60.25 180 bottom
TP7901  TPAD14-OP-GP  [TPAD14-OP]  138.57 73.97 180 bottom
TP7902  TPAD14-OP-GP  [TPAD14-OP]  140.47 59.59 180 bottom
TP7903  TPAD14-OP-GP  [TPAD14-OP]  162.24 55.84 0 top
TP7904  TPAD14-OP-GP  [TPAD14-OP]  161.08 57.31 0 top
TP7905  TPAD14-OP-GP  [TPAD14-OP]  137.07 63.3 180 bottom
TP7906  TPAD14-OP-GP  [TPAD14-OP]  135.71 62.4 180 bottom
TP9102  TPAD14-OP-GP  [TPAD14-OP]  185.34 25.37 270 top
TP9103  TPAD14-OP-GP  [TPAD14-OP]  188.67 29.61 270 top
TP9104  TPAD14-OP-GP  [TPAD14-OP]  189.61 28.78 0 top
TP9105  TPAD14-OP-GP  [TPAD14-OP]  189.74 30.23 0 top
TPAD1  PTWO-CON8-16-GP  [196574-08021-3]  126.6 4.15 180 bottom
U2401  MEC1418-NU-D0-GP  [LQFP128H48]  24.77 20.07 180 bottom
U2502  SY6288C20AAC-GP  [SOT-23-5H56]  168.91 35.22 90 bottom
U2601  NCT7718W-GP  [MSOP8-1H44]  127.29 37.76 0 bottom
U2701  ALC3204-CG-GP-U  [QFN40J5-G3D75H36]  182.71 15.16 90 top
U3301  RTS5100-GR-GP  [QFN32J4-G2D85H36]  8.27 13.8 0 bottom
U4001  TPS22976DPUR-GP  [SON14J3020-G2610H34]  65.32 11.27 90 bottom
U4002  G5027RD1D-GP-U  [DFN8F3-G2517H32]  97.97 33.89 270 top
U4003  G5027RD1D-GP-U  [DFN8F3-G2517H32]  109.05 83.85 0 top
U4006  G5027RD1D-GP-U  [DFN8F3-G2517H32]  136.13 84.45 90 top
U4008  74LVC1G08GW-1-GP  [SC70-5H44]  132.92 33.3 270 bottom
U4302  S-1004NA23I-M5T1U-GP  [SOT-23-5H52]  34.89 58.22 90 bottom
U5501  SY6288C20AAC-GP  [SOT-23-5H56]  60.82 75.98 90 bottom
U6402  74LVC1G08GW-1-GP  [SC70-5H44]  8.94 70.64 180 top
U7002  LNG2DMTR-GP  [LGA12G2H40]  194.24 30.3 180 top
U7101  TUSB546-DCIRNQR-1-GP  [QFN40J4060-G2848H32]  19.97 35.98 180 top
U7201  SN1804044ZBHR-GP  [BGA96G60-1H40]  26.58 62.14 180 bottom
U7202  W25Q80DVSNIG-GP-U  [SOIC8H69]  32.85 68.25 90 bottom
U7418  AONR21321-GP  [PPAK-8P-3232H36]  24.75 76.26 90 top
U7419  NX20P5090UK-GP  [CSP15G154256H24]  24.12 72.85 0 top
U7601  74LVC1G08GW-1-GP  [SC70-5H44]  134.1 74.92 180 bottom
U8502  74LVC1G08GW-1-GP  [SC70-5H44]  146.46 83.5 270 bottom
U8604  74LVC1G08GW-1-GP  [SC70-5H44]  147.57 77.47 180 bottom
U8605  74LVC1G08GW-1-GP  [SC70-5H44]  140.42 77.65 0 bottom
U9101  NPCT750JABYX-GP  [QFN32G5-G3D6H32]  184.59 28.91 270 top
USB1  SKT-USB34-21-GP-U1  [SKT-USB34-124103-U1]  3.03 33.1 90 bottom
VRAM1  H5GQ2H24AFR-T2C-GP  [BGA170D1214H48]  183.5 53.76 270 bottom
VRAM4  H5GQ2H24AFR-T2C-GP  [BGA170D1214H48]  179.2 78.07 90 bottom
WLAN1  SKT-NGFF75P-70-GP-U1  [40-42258-06741RHF-U1]  165.19 22.05 270 bottom
X1801  XTAL-24MHZ-182-GP  [OSC-3225-4P-3H36]  115.79 75.18 180 bottom
X1802  XTAL-32D768KHZ-98-GP  [SMD49-12H34]  105.62 35.15 90 top
X2401  XTAL-32D768KHZ-98-GP  [SMD49-12H34]  13.01 24.92 0 bottom
X7901  XTAL-27MHZ-192-GP  [SMD-OSC38H32]  174.26 39.65 180 bottom

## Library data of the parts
AFTP2402 AFTP2507 AFTP2508 AFTP2601-AFTP2604 AFTP2901-AFTP2904 AFTP3301 AFTP3302 AFTP4301-AFTP4314 AFTP4316 AFTP4317 AFTP5001 AFTP6108-AFTP6115 AFTP6301 AFTP6303 AFTP6304 AFTP6501-AFTP6525 AFTP6529-AFTP6531 AFTP6534-AFTP6539 AFTP6607 AFTP6608 = AFTE14P-75: tolerance: ZZ.AFT14.101
BATT1 = 88231-1201-LP: tolerance: 20.F0818.012
BIOS1 = SOIC8-1H86: tolerance: 072.25128.0B51
C801-C804 C806 C1102-C1111 C1114 C1116 C1117 C1119 C1121 C1218-C1221 C1226 C1227 C1231 C1242 C1244 C1256-C1263 C1268-C1271 C1275-C1279 C1304 C1310-C1313 C1317 C1323-C1326 C1331 C1332 C1341-C1344 C1348 C1349 C1352-C1355 C1367-C1370 C1805 C1806 C2202-C2205 C2209-C2217 C2219 C2222-C2224 C2418 C2525 C3310 C3311 C4031 C4032 C4035 C4038 C4043 C5508 C6402 C6701-C6703 C7210 C7612-C7614 C7622 C7630 C7631 C7807 C7810-C7812 C7815 C7816 C7825 C7826 C8011-C8014 C8018 C8028 C8036 C8105-C8107 C8109-C8112 C8114 C8204-C8206 C8215-C8217 C8219 C8224 C9201 PC4607 PC5151 PC5307 PC8618 PC8623 PC8629 = C402H22: tolerance: 78.10523.5FLDL
C805 C1139-C1142 C1711 C2201 C2206 C2207 C2221 C2406-C2408 C2410-C2416 C2421-C2423 C2428 C2429 C2502 C2503 C2602 C2605 C2608-C2610 C2704 C2706 C2714 C2718 C2721 C2735 C2741 C3303 C3305 C3308 C3309 C4007 C4010 C4034 C4037 C4039 C5501 C5504 C5506 C5507 C5509-C5511 C5516 C5554 C5558 C5701-C5710 C6105 C6107 C6108 C6110 C6307 C6401 C6501 C6504 C6505 C6715 C7005 C7103-C7114 C7206 C7244 C7805 C7808 C7827 C7902 C7905 C7906 C8029 C8034 C8035 C8037 C8044 C8108 C8115-C8125 C8209-C8214 C8220-C8223 C8225 C8226 C8601-C8604 C9104 C9108 C9112 C9113 EC2201 EC8901-EC8907 EC8937 EC8938 PC4467 PC4468 PC5214 PC8607 PC8614 PC8616 = C402H22: tolerance: 78.10421.2FLDL
C807 C1112 C1113 C1115 C1118 C1122 C1128-C1135 C2208 C2220 C5505 C6317 C6318 C7205 C7628 C7818 C7820-C7822 C7935 C8010 C8017 C8027 C8033 PC1001-PC1032 PC1034 PC1036-PC1084 PC4509-PC4512 PC4556-PC4561 PC5106 PC5107 PC5109 PC5113 PC5201 PC5203 PC5205-PC5207 PC5301-PC5303 PC8611 PC8613 PC8620 PC8621 PC8628 PC8631 = C603H40: tolerance: 78.22610.5BLDL
C1120 C1123 C1136-C1138 C1201 C1209-C1211 C1245 C1247-C1249 C1252 C1253 C1265 C1266 C1322 C1333 C1334 C1338 C1350 C1351 C1356 C1371 C1372 C2501 C2601 C2707 C2710 C2711 C2713 C2715 C2717 C2720 C2722 C2907-C2909 C4006 C4008 C4012 C4013 C5517 C5518 C6104 C6109 C7006 C7119 C7208 C7211 C7627 C7629 C7744-C7746 C7817 C7819 C7823 C8038-C8043 C8045 C8046 C8104 C8113 C8207 C8218 C9106 C9109 PC5111 PC5112 PC5154 PC5155 PC8601 PC8622 PC8625-PC8627 PC8630 = C603H36: tolerance: 78.10610.5BLDL
C1214 C1215 C1229 C1230 C1314 C1315 C1329 C1330 C6306 C6308 PC4605 PC4630 PC4634 PC4653 = C402H22: tolerance: 078.47322.02FD
C1250 C1251 C1339 C2517 PC4608 PC4625 PC4626 PC4628 PC4635 PC4652 = C402H22: tolerance: 78.22321.2FLDL
C1605-C1612 C7601-C7608 = C402H22: tolerance: 78.22421.2FLDL
C1701 C7217 C7218 PC5212 = C402H22: tolerance: 78.22124.2FLDL
C1803 C1804 C1807 C1808 = C402H22: tolerance: 78.15034.1FLDL
